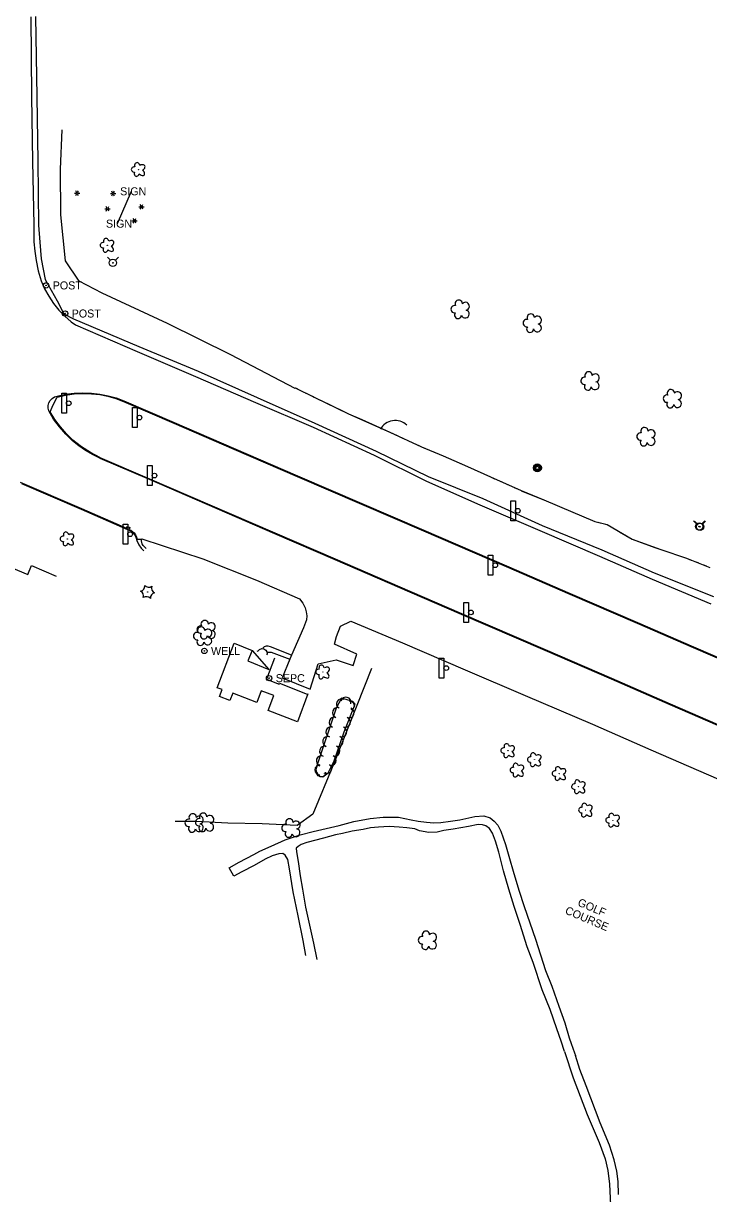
# Model space of a CAD drawing. Extents: x 588843 to 2552415, y 180129 to 269402.
# Drawn here: x 591908 to 592422, y 185815 to 186692 of the extents above; entities that cross this region are included whole.
import ezdxf

# ---------------------------------------------------------------- set-up
doc = ezdxf.new("R2010")
doc.units = 0
for name, color, linetype in [('E_BLD', 7, 'Continuous'), ('E_BLD_HvyDash', 7, 'Continuous'), ('E_LAND_Vegetation', 7, 'Continuous'), ('E_LTG', 7, 'Continuous'), ('E_MISCPROP', 7, 'Continuous'), ('E_MISCPROP_Septic', 7, 'Continuous'), ('E_MISCPROP_Well', 7, 'Continuous'), ('E_MISCPROP_YardLight', 7, 'Continuous'), ('E_RDWY', 7, 'Continuous'), ('E_RDWY_AsphConc', 7, 'Continuous'), ('E_RDWY_C_and_G', 7, 'Continuous'), ('E_RDWY_Gravel', 7, 'Continuous'), ('E_SGN', 7, 'Continuous'), ('E_UTL_WHydrant', 7, 'Continuous'), ('E_WTR_FlowLine', 7, 'Continuous'), ('Level 12', 7, 'Continuous'), ('Level 15', 7, 'Continuous'), ('Level 16', 7, 'Continuous'), ('Level 17', 7, 'Continuous'), ('Level 18', 7, 'Continuous'), ('Level 19', 7, 'Continuous')]:
    doc.layers.add(name, color=color, linetype=linetype)

# ---------------------------------------------------------------- blocks, each defined once
blk = doc.blocks.new('POST')
at = {"layer": 'E_MISCPROP'}
for radius in [4, 0.5]:
    blk.add_circle((0, 0), radius, dxfattribs=at)
blk.add_text('POST', height=12, dxfattribs=at).set_placement((10, -6))
blk = doc.blocks.new('BSGN')
at = {"layer": 'E_SGN'}
blk.add_text('SIGN', height=12, dxfattribs=at).set_placement((-17.1, -6))
blk = doc.blocks.new('CTRE_2')
at = {"layer": 'E_LAND_Vegetation'}
blk.add_circle((0, 0), 0.223, dxfattribs=at)
for centre, start, end in [((-12, 9), 280.2067, 5.9716), ((-13.8, -5.9), 340.2113, 65.9762), ((1.8, 14.9), 220.2113, 305.9762), ((13.8, 5.9), 160.2113, 245.9762), ((-1.8, -14.9), 40.2113, 125.9762), ((12, -9), 100.2511, 185.9272)]:
    blk.add_arc(centre, 7.87, start, end, dxfattribs=at)
blk = doc.blocks.new('DTRE_2')
at = {"layer": 'E_LAND_Vegetation'}
blk.add_circle((-0.2, 0), 0.183, dxfattribs=at)
for centre, major_axis, ratio in [((-5.9, 0.2), (4.93, -0.12), 0.832022), ((-1.9, 5.3), (1.36, -4.98), 0.782863), ((4.1, 2.7), (-5.27, -2.93), 0.691916), ((-2.5, -5.2), (1.8, 4.86), 0.716896), ((3.5, -3.7), (-5.01, 4.58), 0.560249)]:
    blk.add_ellipse(centre, major_axis=major_axis, ratio=ratio, start_param=1.570796, end_param=4.712389, dxfattribs=at)
blk = doc.blocks.new('LPOL_2')
at = {"layer": 'E_LTG'}
for p, q in [((-4, 0), (-1.5, 0)), ((-0.8, 1.3), (-2, 3.5)), ((0.8, 1.3), (2, 3.5)), ((1.5, 0), (4, 0)), ((-2, -3.5), (-0.8, -1.3)), ((2, -3.5), (0.8, -1.3))]:
    blk.add_line(p, q, dxfattribs=at)
for radius in [1.5, 1.5, 1.5, 0.125]:
    blk.add_circle((0, 0), radius, dxfattribs=at)
blk = doc.blocks.new('HYD_1')
at = {"layer": 'E_UTL_WHydrant'}
for p, q in [((-3.8, 3.8), (-8.3, 8.3)), ((3.8, 3.8), (8.3, 8.3))]:
    blk.add_line(p, q, dxfattribs=at)
for radius in [5.48, 0.42]:
    blk.add_circle((0, 0), radius, dxfattribs=at)
blk = doc.blocks.new('SEPC')
at = {"layer": 'E_MISCPROP_Septic'}
for radius in [4, 0.5]:
    blk.add_circle((0, 0), radius, dxfattribs=at)
blk.add_text('SEPC', height=12, dxfattribs=at).set_placement((10, -6))
blk = doc.blocks.new('SGN')
at = {"layer": 'E_SGN'}
blk.add_lwpolyline([(-3.5, -15), (-10.5, -15), (-10.5, 15), (-3.5, 15)], close=True, dxfattribs=at)
blk.add_circle((0, 0), 3.5, dxfattribs=at)
blk = doc.blocks.new('WELL')
at = {"layer": 'E_MISCPROP_Well'}
for radius in [4, 0.5]:
    blk.add_circle((0, 0), radius, dxfattribs=at)
blk.add_text('WELL', height=12, dxfattribs=at).set_placement((10, -6))

msp = doc.modelspace()

# ---------------------------------------------------------------- linework, layer by layer
at = {"layer": 'E_BLD'}
for points in [[(591857.25, 186295.27), (591890.2, 186281.49), (591892.48, 186286.79), (591910.92, 186279.06), (591913.88, 186285.78), (591932.4, 186277.89)], [(592065.76, 186227.51), (592079.17, 186222.01), (592075.97, 186214.18), (592091.71, 186207.88)], [(592099.8, 186197.58), (592120.55, 186189.29)]]:
    msp.add_lwpolyline(points, dxfattribs=at)
at = {"layer": 'E_BLD_HvyDash'}
msp.add_lwpolyline([(592079.17, 186222.01), (592091.71, 186207.88)], dxfattribs=at)
at = {"layer": 'E_MISCPROP_Septic'}
for radius in [2, 0.25]:
    msp.add_circle((592091.93, 186201.27), radius, dxfattribs=at)
at = {"layer": 'E_MISCPROP_Well'}
for radius in [2, 0.25]:
    msp.add_circle((592043.43, 186221.66), radius, dxfattribs=at)
at = {"layer": 'E_RDWY'}
for points in [[(591913.17, 186697.13), (591913.82, 186637.6), (591914.46, 186588.77), (591915.55, 186541.29), (591915.61, 186528.49), (591916.28, 186521.47), (591917.32, 186514.49), (591917.32, 186514.49), (591918.91, 186506.8), (591920.96, 186499.22), (591920.96, 186499.22), (591923.58, 186493.31), (591926.7, 186487.66), (591930.29, 186482.29), (591930.29, 186482.29), (591934.3, 186477.3), (591938.73, 186472.68), (591943.54, 186468.45), (591943.54, 186468.45), (591946.82, 186466.26), (591993.11, 186446.19), (592036.79, 186427.46), (592081.8, 186408.11), (592124.92, 186389.41), (592170.79, 186368.4), (592209.9, 186348.99), (592250.09, 186331.28), (592295.03, 186312.04), (592339.63, 186292.71), (592379.3, 186275.53), (592423.17, 186256.92)], [(591965, 186366.37), (591959.56, 186369.05), (591954.33, 186372.12), (591949.35, 186375.57), (591944.64, 186379.39), (591944.64, 186379.39), (591939.42, 186384.36), (591934.67, 186389.78), (591930.41, 186395.6), (591926.68, 186401.77), (591926.68, 186401.77), (591926.22, 186403.75), (591926.26, 186405.79), (591926.8, 186407.75), (591926.8, 186407.75), (591927.82, 186409.56), (591929.27, 186411.06), (591931.05, 186412.15), (591933.04, 186412.75), (591933.04, 186412.75), (591939.38, 186414.15), (591945.81, 186415.02), (591952.29, 186415.34), (591958.77, 186415.12), (591958.77, 186415.12), (591965.03, 186414.38), (591971.2, 186413.14), (591977.25, 186411.4), (591983.14, 186409.17), (591983.14, 186409.17), (592020.84, 186392.92), (592113.27, 186353.1), (592161.42, 186332.27), (592207.95, 186312.18), (592269.9, 186285.48), (592317.79, 186264.83), (592368.23, 186243), (592410.21, 186224.81), (592455.41, 186205.28)], [(591965, 186366.37), (592002.15, 186350.4), (592096.02, 186309.81), (592141.2, 186290.34), (592189.8, 186269.32), (592234.23, 186250.08), (592298.81, 186222.25), (592348.45, 186200.69), (592392.59, 186181.52), (592435.76, 186162.87)], [(591905.32, 186348.32), (591951.17, 186328.49), (591985.15, 186313.68), (591985.76, 186314.97), (591987.56, 186314.23), (591986.93, 186312.88), (591988.23, 186312.27), (591989.57, 186311.36), (591990.72, 186310.23), (591990.72, 186310.23), (591991.77, 186308.71), (591992.5, 186307.02), (591992.5, 186307.02), (591993.09, 186305.6), (591995.9, 186305.55), (591996.42, 186305.68), (592042.38, 186290.71), (592082.53, 186274.79), (592114.83, 186260.7), (592117.23, 186257.54), (592118.96, 186253.97), (592118.96, 186253.97), (592119.79, 186251.04), (592120.16, 186248.01), (592120.06, 186244.96), (592120.06, 186244.96), (592117.83, 186238.99), (592108.66, 186218.58), (592107.44, 186215.42), (592101.74, 186201.52), (592122.77, 186193.13), (592128.69, 186211.99), (592142.19, 186215.1), (592155.11, 186210.84), (592157.86, 186219.33), (592141.09, 186226.79), (592142.54, 186232.49), (592145.49, 186240.25), (592153.19, 186243.92), (592192.08, 186227.81), (592238.94, 186207.62), (592283.99, 186188.36), (592334.39, 186166.73), (592378.22, 186147.62), (592421.54, 186128.89), (592464.35, 186110.41)]]:
    msp.add_lwpolyline(points, dxfattribs=at)
at = {"layer": 'E_RDWY_AsphConc'}
for points in [[(592083.13, 186221.48), (592083.68, 186221.72), (592084.86, 186222.88), (592086.43, 186223.41), (592088.07, 186223.2), (592088.07, 186223.2), (592089.4, 186222.35), (592090.25, 186221.02), (592090.47, 186219.46), (592090.47, 186219.46), (592089.98, 186218.87)], [(592108.66, 186218.58), (592092.93, 186224.66), (592091.37, 186225.37), (592089.65, 186225.36), (592089.65, 186225.36), (592088.32, 186224.79), (592087.28, 186223.77), (592087.28, 186223.77)], [(592090.49, 186220.67), (592093.52, 186220.78), (592107.44, 186215.42)]]:
    msp.add_lwpolyline(points, dxfattribs=at)
at = {"layer": 'E_RDWY_C_and_G'}
for points in [[(591965.07, 186366.78), (591957.93, 186370.44), (591951.19, 186374.78), (591944.91, 186379.77), (591944.91, 186379.77), (591939.96, 186384.51), (591935.43, 186389.65), (591931.36, 186395.16), (591927.77, 186400.99), (591927.77, 186400.99), (591930.1, 186406.16), (591932.92, 186412.05), (591939.27, 186413.52), (591945.73, 186414.44), (591952.24, 186414.8), (591958.76, 186414.61), (591958.76, 186414.61), (591964.94, 186413.9), (591971.05, 186412.69), (591977.03, 186410.99), (591982.86, 186408.8), (591982.86, 186408.8), (592020.63, 186392.41), (592065.63, 186373.03), (592113.03, 186352.62), (592161.21, 186331.79), (592207.8, 186311.72), (592269.65, 186285.08), (592317.52, 186264.37), (592368, 186242.55), (592410, 186224.4), (592455.14, 186204.8)], [(591965.07, 186366.78), (592002.39, 186350.85), (592047.61, 186331.26), (592096.2, 186310.32), (592141.49, 186290.78), (592190.02, 186269.72), (592234.43, 186250.57), (592299.07, 186222.66), (592348.71, 186201.17), (592392.79, 186182.04), (592435.9, 186163.35)], [(591906.23, 186347.39), (591950.98, 186327.92), (591985.81, 186312.81), (591988.09, 186311.68), (591989.26, 186310.89), (591990.28, 186309.91), (591990.28, 186309.91), (591991.28, 186308.5), (591991.98, 186306.91), (591991.98, 186306.91), (591992.88, 186304.5), (591994.33, 186301.3), (591994.33, 186301.3), (591996.11, 186298.7), (591996.11, 186298.7), (591997.96, 186296.74)], [(591999.88, 186298.41), (591998.4, 186299.92), (591997.44, 186300.83), (591996.76, 186301.95), (591996.76, 186301.95), (591996.42, 186303.03), (591996.34, 186304.16), (591996.34, 186304.16), (591996.42, 186305.68)]]:
    msp.add_lwpolyline(points, dxfattribs=at)
at = {"layer": 'E_RDWY_Gravel'}
msp.add_lwpolyline([(591916.7, 186697.37), (591917.71, 186637.34), (591918.48, 186588.94), (591919.09, 186541.04), (591920, 186528.28), (591921.12, 186515.79), (591924.04, 186500.3), (591932.93, 186484.32), (591938.13, 186474.61), (591945.31, 186470.68), (591994.27, 186450.06), (592038.67, 186431.46), (592083.05, 186411.86), (592126.36, 186392.58), (592172.39, 186371.52), (592211.35, 186352.46), (592252.15, 186335.95), (592296.7, 186315.87), (592341.52, 186297.49), (592380.84, 186280.24), (592425.26, 186262.47)], dxfattribs=at)
at = {"layer": 'E_SGN'}
msp.add_lwpolyline([(591978.18, 186542.14), (591988.83, 186566.39)], dxfattribs=at)
at = {"layer": 'E_UTL_WHydrant'}
for p, q in [((592412.59, 186316.92), (592410.35, 186319.16)), ((592416.43, 186316.92), (592418.67, 186319.16))]:
    msp.add_line(p, q, dxfattribs=at)
for radius in [2.74, 0.21]:
    msp.add_circle((592414.51, 186315), radius, dxfattribs=at)
at = {"layer": 'E_WTR_FlowLine'}
msp.add_lwpolyline([(592111.49, 186418.62), (592063.16, 186443.85), (592015.71, 186467.37), (591966.84, 186490), (591949.63, 186499), (591939.35, 186514.17), (591935.86, 186548.7), (591935.45, 186582.91), (591936.68, 186612.47)], dxfattribs=at)
at = {"layer": 'Level 12'}
for points in [[(592121.14, 186189.48), (592113.23, 186168.62), (592091.15, 186177), (592095.4, 186188.2), (592086.01, 186191.76), (592082.73, 186183.12), (592064.73, 186189.95), (592062.65, 186184.47), (592054.66, 186187.5), (592056.66, 186192.77), (592053.13, 186194.11), (592065.79, 186227.48)], [(592095.97, 186216.21), (592090.02, 186200.53), (592099.62, 186196.89), (592099.86, 186197.52)]]:
    msp.add_lwpolyline(points, dxfattribs=at)
at = {"layer": 'Level 15'}
msp.add_arc((592186.48, 186382.04), 12.5, 45.78065, 152.02021, dxfattribs=at)
at = {"layer": 'Level 16'}
for centre, radius in [((592293.21, 186359.02), 3), ((592293.22, 186359.02), 2.43), ((592293.21, 186358.99), 1.94), ((592293.15, 186358.98), 1.21)]:
    msp.add_circle(centre, radius, dxfattribs=at)
at = {"layer": 'Level 17'}
for points in [[(592168.89, 186208.61), (592140.55, 186137.41), (592124.8, 186099.26), (592113.12, 186090.76), (592086.85, 186092.06), (592060.96, 186092.62), (592037.43, 186093.68), (592021.59, 186093.74)], [(592119.53, 185993.24), (592117.59, 186004.51), (592113.74, 186023.12), (592110.1, 186041.04), (592107.23, 186058.35), (592105.99, 186065.27), (592104.11, 186068.54), (592102.31, 186069.77), (592099.27, 186069.67), (592094.31, 186067.96), (592088.95, 186065.53), (592080.68, 186060.8), (592071.49, 186056), (592065.49, 186052.9), (592062.15, 186059.07), (592069.47, 186063.36), (592080.43, 186069.13), (592085.09, 186071.53), (592093.59, 186075.4), (592104.13, 186080.08), (592115.31, 186083.7), (592125.14, 186086.38), (592144.6, 186090.87), (592155.47, 186093.7), (592167.75, 186096.1), (592177.51, 186097.11), (592189.13, 186097.07), (592198.6, 186095.11), (592203.76, 186094.04), (592210.1, 186093.2), (592215.52, 186092.87), (592220.78, 186093), (592228.12, 186094.06), (592235.02, 186095.07), (592246.37, 186097.6), (592252.92, 186098.05), (592257.72, 186096.45), (592260.78, 186094.13), (592263.41, 186091.1), (592265.84, 186086.46), (592269.18, 186076.52), (592272.14, 186066.17), (592274.95, 186056.44), (592279.37, 186042.38), (592283.37, 186029.99), (592287.47, 186017.89), (592291.76, 186005.6), (592295.51, 185993.69), (592299.33, 185982.05), (592303.91, 185970.27), (592309.36, 185955.32), (592313.71, 185942.83), (592317.08, 185931.64), (592318.42, 185927.36), (592321, 185920.32), (592321.65, 185918.19)], [(592313.39, 185921.26), (592311.11, 185929.04), (592307.67, 185938.43), (592302.83, 185952.93), (592296.67, 185967.61), (592290.07, 185988.02), (592285.54, 185999.86), (592280.18, 186016.55), (592275.78, 186030.02), (592271.79, 186042.93), (592267.67, 186056.88), (592264.31, 186070.74), (592261.69, 186079.15), (592259.62, 186084.96), (592257.21, 186088.44), (592254.48, 186090.53), (592252, 186091.36), (592248.71, 186091.55), (592241.39, 186090.11), (592230.09, 186087.93), (592223.11, 186087.12), (592218.08, 186085.75), (592211.72, 186085.66), (592204.88, 186086.74), (592201.18, 186088.25), (592195.28, 186089.05), (592189.42, 186089.5), (592182.1, 186089.96), (592174.09, 186089.66), (592168.08, 186088.94), (592162.63, 186087.79), (592154.34, 186086.54), (592146.95, 186084.79), (592141.75, 186083.84), (592132.85, 186081.3), (592120.25, 186078.07), (592116.07, 186076.51), (592113.78, 186075.07), (592112.38, 186073.71), (592112.46, 186071.15), (592113.67, 186063.68), (592115.3, 186053.05), (592117.08, 186042.95), (592119.38, 186029.59), (592121.79, 186018.39), (592125.15, 186002.47), (592127.73, 185990.2)], [(592313.39, 185921.26), (592319.97, 185901.55), (592330.55, 185874.15), (592339.38, 185853.16), (592343.93, 185840.84), (592346, 185832.01), (592347.36, 185821.78), (592347.92, 185806.12)], [(592353.88, 185813.95), (592353.68, 185823.76), (592352.79, 185831.65), (592350.66, 185840.09), (592347.14, 185851), (592340.22, 185867.8), (592329.78, 185895.51), (592325, 185907.82), (592321.65, 185918.19)]]:
    msp.add_lwpolyline(points, dxfattribs=at)
at = {"layer": 'Level 18'}
msp.add_lwpolyline([(592128.14, 186136.29), (592127.12, 186132.64), (592128.23, 186128.27), (592132.34, 186127.39), (592136.17, 186130.34), (592140.8, 186139.25), (592148.39, 186160.96), (592156.6, 186181.76), (592154.77, 186183.77), (592146.3, 186186.21), (592142.19, 186178.84), (592128.14, 186136.29)], dxfattribs=at)
for centre, radius, start, end in [((592234.16, 186482.05), 2.78, 1.39455, 209.16754), ((592239.21, 186480.19), 2.97, 278.42366, 139.65754), ((592231.16, 186477.97), 2.78, 78.07156, 279.08261), ((592233.63, 186473.58), 2.61, 140.77971, 358.71232), ((592239.1, 186474.34), 2.97, 196.07447, 79.04774), ((592288.24, 186471.67), 2.78, 1.39455, 209.16754), ((592293.28, 186469.81), 2.97, 278.42366, 139.65754), ((592285.24, 186467.6), 2.78, 78.07156, 279.08261), ((592287.7, 186463.2), 2.61, 140.77971, 358.71232), ((592293.17, 186463.96), 2.97, 196.07447, 79.04774), ((592331.54, 186428.32), 2.78, 1.39455, 209.16754), ((592336.58, 186426.46), 2.97, 278.42366, 139.65754), ((592328.54, 186424.24), 2.78, 78.07156, 279.08261), ((592331, 186419.84), 2.61, 140.77971, 358.71232), ((592336.47, 186420.61), 2.97, 196.07447, 79.04774), ((592390.34, 186410.91), 2.78, 78.07156, 279.08261), ((592393.34, 186414.99), 2.78, 1.39455, 209.16754), ((592398.38, 186413.13), 2.97, 278.42366, 139.65754), ((592392.8, 186406.51), 2.61, 140.77971, 358.71232), ((592398.27, 186407.28), 2.97, 196.07447, 79.04774), ((592370.48, 186382.45), 2.78, 78.07156, 279.08261), ((592373.48, 186386.52), 2.78, 1.39455, 209.16754), ((592378.52, 186384.66), 2.97, 278.42366, 139.65754), ((592372.94, 186378.05), 2.61, 140.77971, 358.71232), ((592378.41, 186378.81), 2.97, 196.07447, 79.04774), ((592043.66, 186241.79), 2.78, 1.39455, 209.16754), ((592040.66, 186237.71), 2.78, 78.07156, 279.08261), ((592041.03, 186236.92), 2.78, 1.39455, 209.16754), ((592046.07, 186235.06), 2.97, 278.42366, 139.65754), ((592048.59, 186234.08), 2.97, 196.07447, 79.04774), ((592048.7, 186239.93), 2.97, 278.42366, 139.65754), ((592038.03, 186232.85), 2.78, 78.07156, 279.08261), ((592040.49, 186228.45), 2.61, 140.77971, 358.71232), ((592043.12, 186233.31), 2.61, 140.77971, 358.71232), ((592045.96, 186229.21), 2.97, 196.07447, 79.04774), ((592146.25, 186181.93), 3.77, 59.85631, 239.84098), ((592149.55, 186183.2), 3.82, 343.94276, 163.92744), ((592152.93, 186180.74), 3.04, 283.34644, 103.33111), ((592143.25, 186175.4), 3.81, 70.39882, 250.3835), ((592151.92, 186175.33), 3.82, 248.47641, 68.46109), ((592140.79, 186168.22), 3.82, 71.72924, 251.71392), ((592149.11, 186168.22), 3.82, 248.46669, 68.45136), ((592136, 186153.71), 3.82, 71.7316, 251.71627), ((592138.39, 186160.97), 3.82, 71.72212, 251.7068), ((592143.78, 186153.82), 3.82, 250.73071, 70.71539), ((592146.37, 186161.04), 3.82, 249.78873, 69.77341), ((592133.6, 186146.46), 3.82, 71.72924, 251.71392), ((592141.26, 186146.61), 3.82, 250.73319, 70.71786), ((592131.2, 186139.25), 3.78, 71.73101, 251.71569), ((592138.51, 186139.67), 3.81, 246.05586, 66.04054), ((592130.04, 186132.51), 3.69, 89.86799, 269.85267), ((592131.27, 186130.69), 3.27, 182.86043, 2.84511), ((592135.07, 186133.36), 3.75, 236.21381, 56.19849), ((592031.66, 186092.77), 2.78, 78.07156, 279.08261), ((592034.66, 186096.84), 2.78, 1.39455, 209.16754), ((592039.49, 186093.22), 2.78, 78.07156, 279.08261), ((592039.7, 186094.99), 2.97, 278.42366, 139.65754), ((592042.49, 186097.3), 2.78, 1.39455, 209.16754), ((592047.53, 186095.44), 2.97, 278.42366, 139.65754), ((592107.2, 186093.06), 2.78, 1.39455, 209.16754), ((592034.12, 186088.37), 2.61, 140.77971, 358.71232), ((592039.59, 186089.13), 2.97, 196.07447, 79.04774), ((592041.95, 186088.82), 2.61, 140.77971, 358.71232), ((592047.42, 186089.59), 2.97, 196.07447, 79.04774), ((592104.2, 186088.98), 2.78, 78.07156, 279.08261), ((592112.13, 186085.34), 2.97, 196.07447, 79.04774), ((592112.24, 186091.2), 2.97, 278.42366, 139.65754), ((592106.66, 186084.58), 2.61, 140.77971, 358.71232), ((592209.59, 186008.85), 2.78, 1.39455, 209.16754), ((592214.63, 186007), 2.97, 278.42366, 139.65754), ((592206.59, 186004.78), 2.78, 78.07156, 279.08261), ((592209.05, 186000.38), 2.61, 140.77971, 358.71232), ((592214.52, 186001.14), 2.97, 196.07447, 79.04774)]:
    msp.add_arc(centre, radius, start, end, dxfattribs=at)
at = {"layer": 'Level 19'}
for points in [[(592111.64, 186419.02), (592125.84, 186411.95), (592151.64, 186399.53), (592182.61, 186385.7), (592206.2, 186374.87), (592222.52, 186368.02), (592240.81, 186360.05), (592258.02, 186352.25), (592280.88, 186341.95), (592298.08, 186335.04), (592319.71, 186325.73), (592336.25, 186318.71), (592345.41, 186316.56), (592364.29, 186305.51), (592385.63, 186297.73), (592404.9, 186291.29), (592422.59, 186284.38)], [(592111.69, 186419), (592115.44, 186417.13)], [(592119.02, 186415.35), (592120.81, 186414.46)], [(592124.4, 186412.67), (592125.84, 186411.95), (592126.19, 186411.79)], [(592129.79, 186410.05), (592131.59, 186409.18)], [(592135.2, 186407.45), (592151.64, 186399.53), (592161.46, 186395.15)], [(592161.46, 186395.15), (592182.61, 186385.7), (592187.91, 186383.27)], [(592191.55, 186381.6), (592193.36, 186380.76)], [(592197, 186379.09), (592198.82, 186378.26)], [(592202.45, 186376.59), (592204.27, 186375.76)], [(592207.93, 186374.14), (592222.52, 186368.02), (592234.6, 186362.76)], [(592234.6, 186362.76), (592240.81, 186360.05), (592258.02, 186352.25), (592261.06, 186350.88)], [(592264.7, 186349.24), (592266.53, 186348.42)], [(592270.17, 186346.77), (592272, 186345.95)], [(592275.64, 186344.31), (592277.47, 186343.49)], [(592281.12, 186341.85), (592298.08, 186335.04), (592307.93, 186330.8)], [(592307.93, 186330.8), (592319.71, 186325.73), (592334.6, 186319.42)], [(592338.4, 186318.21), (592340.34, 186317.75)], [(592344.24, 186316.84), (592345.41, 186316.56), (592346.1, 186316.16)], [(592349.55, 186314.14), (592351.28, 186313.13)], [(592354.73, 186311.11), (592364.29, 186305.51), (592381.13, 186299.38)], [(592381.13, 186299.38), (592385.63, 186297.73), (592404.9, 186291.29), (592408.52, 186289.88)], [(592412.25, 186288.42), (592414.11, 186287.7)], [(592417.84, 186286.24), (592419.7, 186285.51)]]:
    msp.add_lwpolyline(points, dxfattribs=at)

# ---------------------------------------------------------------- block references
at = {"layer": 'E_LAND_Vegetation', "xscale": 0.5, "yscale": 0.5}
for name, p in [('DTRE_2', (591994.06, 186582.69)), ('DTRE_2', (591970.73, 186525.88)), ('DTRE_2', (591940.7, 186305.71)), ('CTRE_2', (592000.84, 186265.94)), ('DTRE_2', (592132.39, 186205.89)), ('DTRE_2', (592271.18, 186146.89)), ('DTRE_2', (592291.08, 186140.12)), ('DTRE_2', (592278.09, 186132.29)), ('DTRE_2', (592309.64, 186129.71)), ('DTRE_2', (592324.22, 186119.84)), ('DTRE_2', (592329.49, 186102.27)), ('DTRE_2', (592349.83, 186094.75))]:
    msp.add_blockref(name, p, dxfattribs=at)
at = {"layer": 'E_LTG', "xscale": 0.5, "yscale": 0.5}
msp.add_blockref('LPOL_2', (591948.01, 186565), dxfattribs=at)
at = {"layer": 'E_MISCPROP', "xscale": 0.5, "yscale": 0.5}
for p in [(591924.71, 186495.82), (591938.93, 186474.75)]:
    msp.add_blockref('POST', p, dxfattribs=at)
at = {"layer": 'E_MISCPROP_Septic', "xscale": 0.5, "yscale": 0.5}
msp.add_blockref('SEPC', (592091.93, 186201.27), dxfattribs=at)
at = {"layer": 'E_MISCPROP_Well', "xscale": 0.5, "yscale": 0.5}
msp.add_blockref('WELL', (592043.43, 186221.66), dxfattribs=at)
at = {"layer": 'E_MISCPROP_YardLight', "xscale": 0.5, "yscale": 0.5}
for p in [(591974.98, 186564.71), (591970.78, 186553.3), (591996.32, 186554.84), (591991.13, 186544.35)]:
    msp.add_blockref('LPOL_2', p, dxfattribs=at)
at = {"layer": 'E_SGN', "xscale": 0.5, "yscale": 0.5}
for name, p in [('BSGN', (591988.83, 186566.39)), ('BSGN', (591978.18, 186542.14)), ('SGN', (591941.73, 186407.43)), ('SGN', (591994.76, 186396.66)), ('SGN', (592006.03, 186353.22)), ('SGN', (592278.45, 186326.85)), ('SGN', (591987.74, 186309.23)), ('SGN', (592261.52, 186285.92)), ('SGN', (592243.35, 186250.62)), ('SGN', (592224.86, 186208.83))]:
    msp.add_blockref(name, p, dxfattribs=at)
at = {"layer": 'E_UTL_WHydrant', "xscale": 0.5, "yscale": 0.5}
for p in [(591974.84, 186512.75), (592415.15, 186314.83), (592415.15, 186314.83)]:
    msp.add_blockref('HYD_1', p, dxfattribs=at)

# ---------------------------------------------------------------- texts
at = {"layer": 'Level 17'}
for s, p in [('GOLF', (592322.82, 186030.93)), ('COURSE', (592313.41, 186024.89))]:
    msp.add_text(s, height=6, rotation=337, dxfattribs=at).set_placement(p)

doc.saveas('drawing.dxf')
